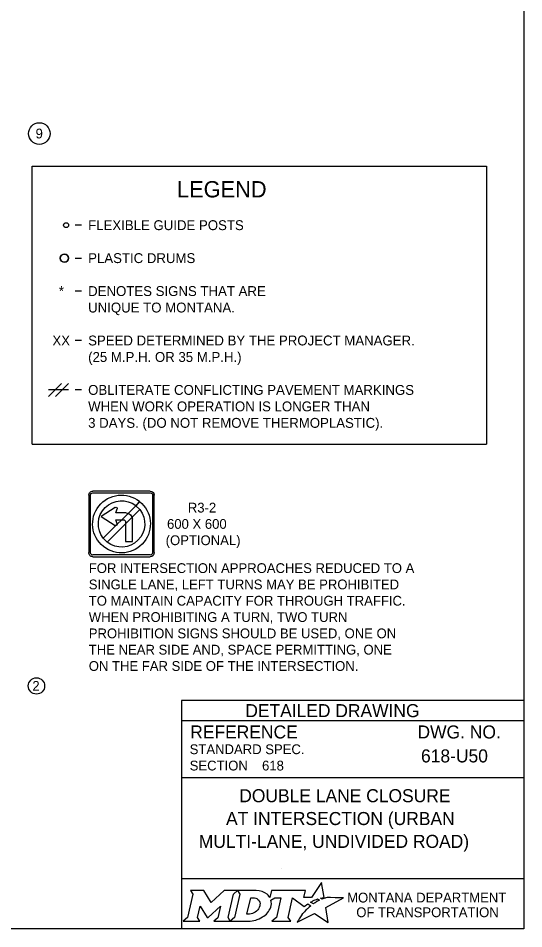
# Model space of a CAD drawing. Extents: x 49991.4 to 50021, y 49987.6 to 50011.4.
# Drawn here: x 50013.65 to 50016.75, y 49987.8 to 49993.38 of the extents above; entities that cross this region are included whole.
import ezdxf

# ---------------------------------------------------------------- set-up
doc = ezdxf.new("R2010")
doc.units = 0
for name, color, linetype in [('Default', 7, 'Continuous'), ('Level 1', 7, 'Continuous'), ('Level 2', 7, 'Continuous'), ('Level 25', 7, 'Continuous'), ('Level 5', 7, 'Continuous')]:
    doc.layers.add(name, color=color, linetype=linetype)

# ---------------------------------------------------------------- blocks, each defined once
blk = doc.blocks.new('R3.1')
at = {"layer": 'Level 25'}
for p, q in [((-35.8, 39.5), (38.3, 39.5)), ((38.3, 37.3), (-35.8, 37.3)), ((-41.1, 34.2), (-38.9, 34.2)), ((-38.9, 34.2), (-41.1, 34.2)), ((-41.1, -39.9), (-41.1, 34.2)), ((-41.1, 34.2), (-38.9, 34.2)), ((-38.9, 34.2), (-38.9, -39.9)), ((-21.9, 26.2), (-17.3, 20.7)), ((-17.2, 20.8), (-21.8, 26.3)), ((41.4, -39.9), (41.4, 34.2)), ((43.6, 34.2), (43.6, -39.9)), ((-17.3, 20.7), (-22.3, 15.7)), ((-17.3, 20.7), (-22.3, 15.7)), ((-22.3, 15.7), (19.8, -26.4)), ((24.8, -21.4), (-17.3, 20.7)), ((8.4, 11.3), (6.7, 16.5)), ((9.3, 18.5), (27.7, 6.9)), ((9.3, 18.5), (9.3, 18.5)), ((-12.9, -25.7), (-12.9, 3.3)), ((-4.9, 11.3), (8.4, 11.3)), ((8.4, 2.5), (-1.1, 2.5)), ((6.7, -2.7), (8.4, 2.5)), ((27.7, 6.9), (9.3, -4.7)), ((-4.1, -0.5), (-4.1, -25.7)), ((19.8, -26.4), (24.8, -21.4)), ((19.8, -26.4), (24.8, -21.4)), ((-4.1, -25.7), (-12.9, -25.7)), ((-35.8, -42.9), (38.3, -42.9)), ((38.3, -45.2), (-35.8, -45.2))]:
    blk.add_line(p, q, dxfattribs=at)
for centre, radius, start, end in [((-35.8, 34.2), 5.29, 90, 180), ((-35.8, 34.2), 3.09, 90, 180), ((38.3, 34.2), 5.29, 0, 90), ((38.3, 34.2), 3.09, 0, 90), ((1.3, -2.9), 37.3, 128.573, 128.3407), ((1.2, -2.8), 30, 321.7571, 127.9547), ((1.2, -2.8), 30, 141.7565, 308.2429), ((8.4, 17), 1.75, 57.757, 197.6186), ((1.2, -2.8), 30, 44.2869, 44.4163), ((-4.9, 3.3), 8, 90, 180), ((-1.1, -0.5), 3, 90, 180), ((8.4, -3.2), 1.75, 162.3804, 302.2438), ((1.2, -2.8), 30, 220.8564, 220.8714), ((-35.8, -39.9), 5.29, 180, 270), ((-35.8, -39.9), 3.09, 180, 270), ((38.3, -39.9), 5.29, 270, 0), ((38.3, -39.9), 3.09, 270, 0)]:
    blk.add_arc(centre, radius, start, end, dxfattribs=at)

msp = doc.modelspace()

# ---------------------------------------------------------------- linework, layer by layer
at = {"layer": 'Default'}
for points in [[(50015.5126, 49987.9811), (50015.5023, 49987.9867), (50015.5139, 49987.9895), (50015.5255, 49987.9915), (50015.5081, 49988.0816), (50015.4486, 49987.9903), (50015.4013, 49987.9896), (50015.4116, 49988.0337), (50015.2024, 49988.0338), (50015.1923, 49987.9913), (50015.1865, 49987.9996)], [(50014.7056, 49988.0338), (50014.7197, 49988.0104), (50014.6862, 49987.8671), (50014.6605, 49987.8446), (50014.7621, 49987.8446), (50014.7486, 49987.8674), (50014.7648, 49987.9375), (50014.8085, 49987.8685), (50014.8138, 49987.8685), (50014.8889, 49987.938), (50014.8725, 49987.8669), (50014.8478, 49987.8449), (50014.9494, 49987.8449), (50014.9356, 49987.8682), (50014.9688, 49988.0106)], [(50014.9688, 49988.0106), (50014.9941, 49988.0338), (50014.9117, 49988.0338), (50014.8321, 49987.9608), (50014.7876, 49988.0335), (50014.7056, 49988.0338)], [(50015.1077, 49988.0338), (50014.9941, 49988.0338), (50015.0088, 49988.0109), (50014.9749, 49987.8671), (50014.9494, 49987.8449), (50015.06, 49987.8449)], [(50015.1317, 49987.9471), (50015.1305, 49987.939), (50015.1273, 49987.9297), (50015.1231, 49987.9215), (50015.1175, 49987.914), (50015.111, 49987.9071), (50015.1031, 49987.9008), (50015.0948, 49987.8961), (50015.0857, 49987.8922), (50015.0766, 49987.8899), (50015.0674, 49987.889), (50015.0515, 49987.889), (50015.0751, 49987.989), (50015.0911, 49987.989), (50015.0987, 49987.9884), (50015.1063, 49987.9865), (50015.1129, 49987.9835), (50015.119, 49987.9793), (50015.1238, 49987.9743), (50015.1275, 49987.9683), (50015.1302, 49987.9621), (50015.1318, 49987.9547), (50015.1318, 49987.9517), (50015.1317, 49987.9471)], [(50015.1991, 49987.9747), (50015.2237, 49987.9878), (50015.2606, 49987.9878), (50015.232, 49987.8673), (50015.2045, 49987.8446), (50015.3207, 49987.8446), (50015.3037, 49987.8675), (50015.3319, 49987.9877), (50015.4032, 49987.936), (50015.4243, 49987.9511), (50015.444, 49987.9402)], [(50015.3882, 49987.8843), (50015.3729, 49987.8599), (50015.3682, 49987.8524), (50015.3624, 49987.8438), (50015.3601, 49987.8395), (50015.4654, 49987.8926), (50015.5493, 49987.8375), (50015.5362, 49987.9302), (50015.6431, 49987.9886), (50015.5938, 49987.9894), (50015.5637, 49987.9898), (50015.5429, 49987.9901), (50015.5361, 49987.9886), (50015.5312, 49987.9874), (50015.5228, 49987.9851), (50015.5126, 49987.9811)], [(50015.4622, 49987.9535), (50015.4598, 49987.9518), (50015.4415, 49987.9614), (50015.4518, 49987.9671), (50015.4559, 49987.9693), (50015.4645, 49987.9733), (50015.4702, 49987.9759), (50015.4781, 49987.9789), (50015.4854, 49987.9816), (50015.4972, 49987.9742), (50015.4932, 49987.9721), (50015.4886, 49987.9696), (50015.4844, 49987.9674), (50015.4794, 49987.9645), (50015.4775, 49987.9634), (50015.4748, 49987.9618), (50015.4723, 49987.9604), (50015.47, 49987.9588), (50015.4674, 49987.957), (50015.4647, 49987.9552), (50015.4622, 49987.9535)], [(50015.4021, 49987.9004), (50015.4021, 49987.9004)], [(50015.1057, 49987.8522), (50015.1141, 49987.8548), (50015.1271, 49987.8602), (50015.1475, 49987.8712)]]:
    msp.add_lwpolyline(points, dxfattribs=at)
for centre, radius, start, end in [((50015.1308, 49987.9554), 0.0709, 339.5329, 15.8582), ((50015.0868, 49987.9727), 0.1183, 300.9103, 339.1383)]:
    msp.add_arc(centre, radius, start, end, dxfattribs=at)
for centre, major_axis, ratio, start_param, end_param in [((50015.1056, 49987.9864), (0.0834, -0.0037), 0.568097, 0.61298, 1.570796), ((50015.1612, 49987.9937), (0.0361, -0.0295), 0.469099, 1.225588, 1.570796), ((50015.4329, 49987.9305), (-0.0112, -0.0097), 0.021651, 3.157348, 6.283185), ((50015.3952, 49987.8923), (-0.00694, -0.00806), 0.008222, 0, 3.137361), ((50015.4119, 49987.9106), (-0.0098, -0.0102), 0.016458, 3.141593, 6.279097), ((50015.0603, 49987.9932), (0, 0.1484), 0.987302, 3.139398, 3.456847)]:
    msp.add_ellipse(centre, major_axis=major_axis, ratio=ratio, start_param=start_param, end_param=end_param, dxfattribs=at)
at = {"layer": 'Level 1'}
for p, q in [((50013.8335, 49991.062), (50013.9143, 49991.1428)), ((50013.8763, 49991.062), (50013.9571, 49991.1428)), ((50013.9571, 49991.1024), (50013.8335, 49991.1024)), ((50016.3862, 49988.8587), (50016.3862, 49988.8587)), ((50015.1444, 49988.7993), (50015.1444, 49988.7993)), ((50015.7001, 49988.4747), (50015.7001, 49988.4747)), ((50015.2654, 49988.1691), (50015.2654, 49988.1691))]:
    msp.add_line(p, q, dxfattribs=at)
msp.add_lwpolyline([(49999.3835, 49998.9992), (50016.7501, 49998.9992), (50016.7501, 49987.7988), (49999.3835, 49987.7988)], close=True, dxfattribs=at)
for centre, radius in [((50013.942, 49992.1124), 0.0152), ((50013.9319, 49991.9104), 0.0252)]:
    msp.add_circle(centre, radius, dxfattribs=at)
for start, end in [(360, 180), (180, 0)]:
    msp.add_arc((50013.9319, 49991.9104), 0.0252, start, end, dxfattribs=at)
at = {"layer": 'Level 2'}
for p, q in [((50013.7335, 49990.7701), (50013.7335, 49992.4741)), ((50014.0375, 49992.1124), (50013.9971, 49992.1124)), ((50013.9971, 49991.9104), (50014.0375, 49991.9104)), ((50014.0375, 49991.7084), (50013.9971, 49991.7084)), ((50014.0375, 49991.4054), (50013.9971, 49991.4054)), ((50014.0375, 49991.1024), (50013.9971, 49991.1024)), ((50013.7335, 49990.7701), (50016.5203, 49990.7701))]:
    msp.add_line(p, q, dxfattribs=at)
msp.add_lwpolyline([(50013.7335, 49992.4741), (50016.5203, 49992.4741), (50016.5203, 49990.7701)], dxfattribs=at)
for centre, radius in [((50013.7782, 49992.6742), 0.0662), ((50013.7606, 49989.2877), 0.0501)]:
    msp.add_circle(centre, radius, dxfattribs=at)
at = {"layer": 'Level 5'}
for p, q in [((50016.7501, 49989.1988), (50014.6501, 49989.1988)), ((50014.6501, 49989.1988), (50014.6501, 49987.7988)), ((50016.7501, 49989.0738), (50014.6501, 49989.0738)), ((50016.3862, 49988.8587), (50016.3862, 49988.8587)), ((50015.1444, 49988.7993), (50015.1444, 49988.7993)), ((50016.7501, 49988.7238), (50014.6501, 49988.7238)), ((50015.7001, 49988.4747), (50015.7001, 49988.4747)), ((50016.7501, 49988.1057), (50014.6501, 49988.1057))]:
    msp.add_line(p, q, dxfattribs=at)

# ---------------------------------------------------------------- block references
at = {"layer": 'Level 1', "xscale": 0.004746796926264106, "yscale": -0.004746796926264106, "rotation": 179.9999999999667}
msp.add_blockref('R3.1', (50014.2882, 49990.2943), dxfattribs=at)

# ---------------------------------------------------------------- texts
at = {"layer": 'Default'}
for s, p in [('MONTANA DEPARTMENT', (50015.6663, 49987.96)), ('OF TRANSPORTATION', (50015.7225, 49987.87))]:
    msp.add_text(s, height=0.06, dxfattribs=at).set_placement(p)
at = {"layer": 'Level 2'}
for s, height, p in [('9', 0.0601, (50013.7551, 49992.6443)), ('LEGEND', 0.1, (50014.6225, 49992.2827)), ('FLEXIBLE GUIDE POSTS', 0.0606, (50014.0775, 49992.0821)), ('PLASTIC DRUMS', 0.0606, (50014.0775, 49991.8801)), ('*', 0.0607, (50013.8978, 49991.678)), ('DENOTES SIGNS THAT ARE', 0.0606, (50014.0775, 49991.6781)), ('UNIQUE TO MONTANA.', 0.0606, (50014.0775, 49991.5771)), ('XX', 0.0606, (50013.8583, 49991.3751)), ('SPEED DETERMINED BY THE PROJECT MANAGER.', 0.0606, (50014.0775, 49991.3751)), ('(25 M.P.H. OR 35 M.P.H.)', 0.0606, (50014.0775, 49991.2741)), ('OBLITERATE CONFLICTING PAVEMENT MARKINGS', 0.0606, (50014.0775, 49991.0721)), ('WHEN WORK OPERATION IS LONGER THAN', 0.0606, (50014.0775, 49990.9711)), ('3 DAYS. (DO NOT REMOVE THERMOPLASTIC).', 0.0606, (50014.0775, 49990.8701)), ('R3-2', 0.06, (50014.6891, 49990.3508)), ('600 X 600', 0.06, (50014.5615, 49990.2508)), ('(OPTIONAL)', 0.06, (50014.5532, 49990.1508)), ('FOR INTERSECTION APPROACHES REDUCED TO A', 0.06, (50014.0814, 49989.9799)), ('SINGLE LANE, LEFT TURNS MAY BE PROHIBITED', 0.06, (50014.0814, 49989.8799)), ('TO MAINTAIN CAPACITY FOR THROUGH TRAFFIC.', 0.06, (50014.0814, 49989.7799)), ('WHEN PROHIBITING A TURN, TWO TURN ', 0.06, (50014.0814, 49989.6799)), ('PROHIBITION SIGNS SHOULD BE USED, ONE ON ', 0.06, (50014.0814, 49989.5799)), ('THE NEAR SIDE AND, SPACE PERMITTING, ONE ', 0.06, (50014.0814, 49989.4799)), ('ON THE FAR SIDE OF THE INTERSECTION.', 0.06, (50014.0814, 49989.3799)), ('2', 0.06, (50013.7354, 49989.2577)), ('618-U50', 0.08, (50016.1196, 49988.8187)), ('618', 0.06, (50015.1444, 49988.7693)), (' DOUBLE LANE CLOSURE', 0.08, (50014.9747, 49988.5747)), (' AT INTERSECTION (URBAN ', 0.08, (50014.8937, 49988.4347)), ('MULTI-LANE, UNDIVIDED ROAD)', 0.08, (50014.7562, 49988.2947))]:
    msp.add_text(s, height=height, dxfattribs=at).set_placement(p)
at = {"layer": 'Level 5'}
for s, height, p in [('DETAILED DRAWING', 0.0799, (50015.0418, 49989.0963)), ('REFERENCE', 0.08, (50014.7037, 49988.9654)), ('DWG. NO.', 0.08, (50016.0979, 49988.9654)), ('STANDARD SPEC.', 0.06, (50014.7004, 49988.8694)), ('SECTION', 0.06, (50014.7004, 49988.7694))]:
    msp.add_text(s, height=height, dxfattribs=at).set_placement(p)

doc.saveas('drawing.dxf')
